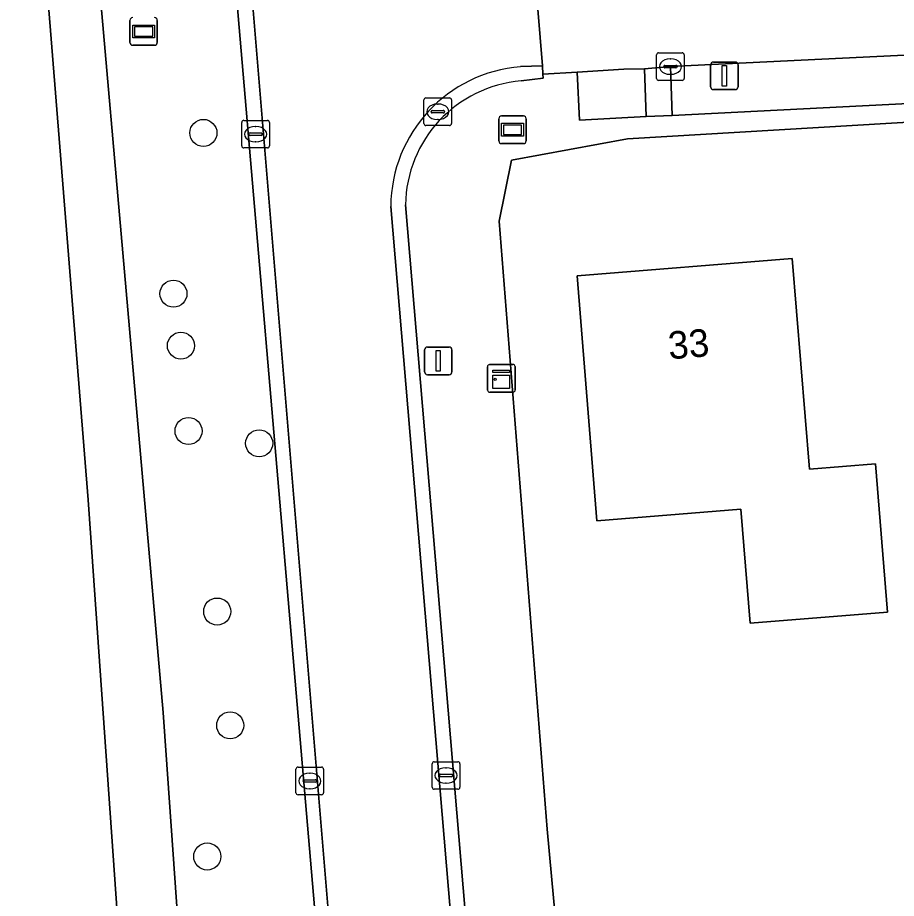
# Model space of a CAD drawing. Extents: x 162661 to 163484, y 380247 to 381230.
# Drawn here: x 163096.7 to 163128.5, y 380681.45 to 380713.34 of the extents above; entities that cross this region are included whole.
import ezdxf

# ---------------------------------------------------------------- set-up
doc = ezdxf.new("R2010")
doc.units = 0
for name, color, linetype in [('IMGEO_Boom', 7, 'Continuous'), ('IMGEO_Erf', 7, 'Continuous'), ('IMGEO_Groenvoorziening', 7, 'Continuous'), ('IMGEO_Kast', 7, 'Continuous'), ('IMGEO_Kolk', 7, 'Continuous'), ('IMGEO_Lichtmast', 7, 'Continuous'), ('IMGEO_Pand', 7, 'Continuous'), ('IMGEO_Pand_nummerreeks', 7, 'Continuous'), ('IMGEO_Parkeervlak_halfverhard', 7, 'Continuous'), ('IMGEO_Rijbaan_lokaal_gesloten', 7, 'Continuous'), ('IMGEO_Rijbaan_lokaal_open', 7, 'Continuous'), ('IMGEO_Straatnaambord', 7, 'Continuous'), ('IMGEO_Verklikker', 7, 'Continuous'), ('IMGEO_Voetpad_open', 7, 'Continuous')]:
    doc.layers.add(name, color=color, linetype=linetype)

msp = doc.modelspace()

# ---------------------------------------------------------------- linework, layer by layer
at = {"layer": 'IMGEO_Boom'}
for centre in [(163103.422, 380709.163), (163102.337, 380703.343), (163102.606, 380701.459), (163102.882, 380698.371), (163105.439, 380697.926), (163103.92, 380691.838), (163104.39, 380687.716), (163103.559, 380682.97)]:
    msp.add_circle(centre, 0.489, dxfattribs=at)
at = {"layer": 'IMGEO_Erf'}
for points in [[(163099.255, 380695.881), (163097.801, 380713.922), (163097.793, 380714.023), (163096.429, 380713.908), (163093.637, 380713.673), (163059.39, 380710.863), (163058.898, 380719.038), (163058.632, 380719.002), (163032.944, 380715.524), (163037.315, 380653.943), (163063.757, 380657.004), (163064.055, 380657.039), (163063.669, 380662.881), (163100.129, 380668.22), (163101.186, 380668.378), (163101.16, 380668.743)], [(163123.212, 380691.412), (163122.877, 380695.542), (163117.662, 380695.119), (163116.944, 380703.984), (163124.734, 380704.615), (163125.352, 380696.988), (163127.743, 380697.181), (163128.178, 380691.814)]]:
    msp.add_lwpolyline(points, close=True, dxfattribs=at)
msp.add_lwpolyline([(163169.175, 380712.083), (163165.538, 380711.722), (163118.769, 380708.949), (163114.577, 380708.178), (163114.12, 380705.969), (163115.857, 380683.956), (163117.643, 380664.6), (163117.707, 380663.313), (163117.885, 380659.75), (163116.14, 380660.353), (163114.938, 380658.973), (163115.539, 380658.257), (163116.937, 380656.59), (163121.165, 380651.709), (163126.069, 380600.194)], dxfattribs=at)
at = {"layer": 'IMGEO_Groenvoorziening'}
msp.add_lwpolyline([(163104.682, 380713.401), (163104.584, 380714.593), (163103.718, 380714.52), (163103.473, 380714.5), (163099.679, 380714.181), (163101.96, 380688.185), (163103.318, 380669.012), (163103.34, 380668.7), (163107.281, 380669.289), (163107.167, 380670.648), (163108.355, 380670.753), (163107.991, 380674.665)], close=True, dxfattribs=at)
for points in [[(163115.857, 380683.956), (163114.12, 380705.969), (163114.577, 380708.178), (163118.769, 380708.949), (163165.538, 380711.722), (163165.457, 380712.44), (163162.021, 380712.179), (163153.17, 380711.561), (163152.219, 380711.484), (163142.245, 380710.899), (163120.382, 380709.791), (163119.45, 380709.752), (163117.031, 380709.623), (163116.953, 380711.361), (163115.709, 380711.284), (163115.715, 380711.141), (163114.917, 380711.042)], [(163110.734, 380706.554), (163112.985, 380679.977), (163114.376, 380665.012), (163117.707, 380663.313), (163117.643, 380664.6), (163115.857, 380683.956)]]:
    msp.add_lwpolyline(points, dxfattribs=at)
msp.add_arc((163115.301, 380706.491), 4.568, 94.8247, 179.2044, dxfattribs=at)
at = {"layer": 'IMGEO_Kast'}
for p, q in [((163113.778, 380700.779), (163114.619, 380700.779)), ((163114.619, 380700.779), (163113.778, 380700.779)), ((163113.703, 380699.854), (163113.703, 380700.695)), ((163113.703, 380700.695), (163113.703, 380699.854)), ((163114.703, 380700.704), (163114.703, 380699.863)), ((163114.703, 380699.863), (163114.703, 380700.704)), ((163114.628, 380699.779), (163113.787, 380699.779)), ((163113.787, 380699.779), (163114.628, 380699.779))]:
    msp.add_line(p, q, dxfattribs=at)
for points in [[(163113.898, 380700.569), (163114.498, 380700.569), (163114.498, 380700.484), (163113.898, 380700.484), (163113.898, 380700.569)], [(163113.898, 380700.394), (163114.498, 380700.394), (163114.498, 380699.905), (163113.898, 380699.905), (163113.898, 380700.394)]]:
    msp.add_lwpolyline(points, dxfattribs=at)
msp.add_circle((163113.982, 380700.243), 0.0377, dxfattribs=at)
for centre, start, end in [((163113.781, 380700.701), 92.4484, 184.2845), ((163113.781, 380700.701), 92.4484, 184.2845), ((163114.625, 380700.701), 2.4484, 94.2845), ((163114.625, 380700.701), 2.4484, 94.2845), ((163113.781, 380699.857), 182.4484, 274.2845), ((163113.781, 380699.857), 182.4484, 274.2845), ((163114.625, 380699.857), 272.4484, 4.2845), ((163114.625, 380699.857), 272.4484, 4.2845)]:
    msp.add_arc(centre, 0.0779, start, end, dxfattribs=at)
at = {"layer": 'IMGEO_Kolk'}
for p, q in [((163119.823, 380711.137), (163119.823, 380711.989)), ((163119.898, 380712.063), (163120.75, 380712.063)), ((163120.824, 380711.989), (163120.824, 380711.137)), ((163120.311, 380711.843), (163120.336, 380711.843)), ((163120.082, 380711.557), (163120.082, 380711.569)), ((163120.52, 380711.52), (163120.122, 380711.52)), ((163120.125, 380711.606), (163120.523, 380711.606)), ((163120.566, 380711.569), (163120.566, 380711.557)), ((163120.75, 380711.063), (163119.898, 380711.063)), ((163120.334, 380711.283), (163120.309, 380711.283)), ((163111.402, 380709.502), (163111.402, 380710.354)), ((163111.477, 380710.428), (163112.329, 380710.428)), ((163112.403, 380710.354), (163112.403, 380709.502)), ((163111.89, 380710.208), (163111.915, 380710.208)), ((163111.661, 380709.922), (163111.661, 380709.934)), ((163112.099, 380709.885), (163111.701, 380709.885)), ((163111.704, 380709.971), (163112.102, 380709.971)), ((163112.145, 380709.934), (163112.145, 380709.922)), ((163104.81, 380708.691), (163104.81, 380709.543)), ((163104.885, 380709.617), (163105.737, 380709.617)), ((163105.298, 380709.397), (163105.323, 380709.397)), ((163105.811, 380709.543), (163105.811, 380708.691)), ((163112.329, 380709.428), (163111.477, 380709.428)), ((163111.913, 380709.648), (163111.888, 380709.648)), ((163105.069, 380709.111), (163105.069, 380709.123)), ((163105.507, 380709.074), (163105.109, 380709.074)), ((163105.112, 380709.16), (163105.51, 380709.16)), ((163105.553, 380709.123), (163105.553, 380709.111)), ((163105.321, 380708.837), (163105.296, 380708.837)), ((163105.737, 380708.617), (163104.885, 380708.617)), ((163106.77, 380685.278), (163106.77, 380686.13)), ((163106.845, 380686.204), (163107.697, 380686.204)), ((163107.771, 380686.13), (163107.771, 380685.278)), ((163111.701, 380685.476), (163111.701, 380686.328)), ((163111.776, 380686.402), (163112.628, 380686.402)), ((163112.189, 380686.182), (163112.214, 380686.182)), ((163112.702, 380686.328), (163112.702, 380685.476)), ((163107.258, 380685.984), (163107.283, 380685.984)), ((163111.96, 380685.896), (163111.96, 380685.908)), ((163112.398, 380685.859), (163112, 380685.859)), ((163112.003, 380685.945), (163112.401, 380685.945)), ((163112.444, 380685.908), (163112.444, 380685.896)), ((163107.029, 380685.698), (163107.029, 380685.71)), ((163107.467, 380685.661), (163107.069, 380685.661)), ((163107.072, 380685.747), (163107.47, 380685.747)), ((163107.513, 380685.71), (163107.513, 380685.698)), ((163112.212, 380685.622), (163112.187, 380685.622)), ((163107.697, 380685.204), (163106.845, 380685.204)), ((163107.281, 380685.424), (163107.256, 380685.424)), ((163112.628, 380685.402), (163111.776, 380685.402))]:
    msp.add_line(p, q, dxfattribs=at)
for points in [[(163119.823, 380711.137), (163119.823, 380711.989)], [(163119.898, 380712.063), (163120.75, 380712.063)], [(163120.824, 380711.989), (163120.824, 380711.137)], [(163120.75, 380711.063), (163119.898, 380711.063)], [(163111.402, 380709.502), (163111.402, 380710.354)], [(163111.477, 380710.428), (163112.329, 380710.428)], [(163112.403, 380710.354), (163112.403, 380709.502)], [(163104.81, 380708.691), (163104.81, 380709.543)], [(163104.885, 380709.617), (163105.737, 380709.617)], [(163105.811, 380709.543), (163105.811, 380708.691)], [(163112.329, 380709.428), (163111.477, 380709.428)], [(163105.737, 380708.617), (163104.885, 380708.617)], [(163106.77, 380685.278), (163106.77, 380686.13)], [(163106.845, 380686.204), (163107.697, 380686.204)], [(163107.771, 380686.13), (163107.771, 380685.278)], [(163111.701, 380685.476), (163111.701, 380686.328)], [(163111.776, 380686.402), (163112.628, 380686.402)], [(163112.702, 380686.328), (163112.702, 380685.476)], [(163107.697, 380685.204), (163106.845, 380685.204)], [(163112.628, 380685.402), (163111.776, 380685.402)]]:
    msp.add_lwpolyline(points, dxfattribs=at)
for centre, radius, start, end in [((163119.9, 380711.987), 0.0765, 91.552, 178.448), ((163119.9, 380711.987), 0.0765, 91.552, 178.448), ((163120.748, 380711.987), 0.0765, 1.552, 88.448), ((163120.748, 380711.987), 0.0765, 1.552, 88.448), ((163120.122, 380711.566), 0.0403, 85.8775, 175.7526), ((163120.119, 380711.556), 0.0366, 178.938, 274.7102), ((163120.523, 380711.563), 0.043, 264.8664, 352.4533), ((163120.527, 380711.568), 0.0386, 1.7309, 96.639), ((163119.9, 380711.139), 0.0765, 181.552, 268.448), ((163119.9, 380711.139), 0.0765, 181.552, 268.448), ((163120.748, 380711.139), 0.0765, 271.552, 358.448), ((163120.748, 380711.139), 0.0765, 271.552, 358.448), ((163111.479, 380710.352), 0.0765, 91.552, 178.448), ((163111.479, 380710.352), 0.0765, 91.552, 178.448), ((163112.327, 380710.352), 0.0765, 1.552, 88.448), ((163112.327, 380710.352), 0.0765, 1.552, 88.448), ((163111.701, 380709.931), 0.0403, 85.8775, 175.7526), ((163111.698, 380709.921), 0.0366, 178.938, 274.7102), ((163112.102, 380709.928), 0.043, 264.8664, 352.4533), ((163112.106, 380709.933), 0.0386, 1.7309, 96.639), ((163104.887, 380709.541), 0.0765, 91.552, 178.448), ((163104.887, 380709.541), 0.0765, 91.552, 178.448), ((163105.735, 380709.541), 0.0765, 1.552, 88.448), ((163105.735, 380709.541), 0.0765, 1.552, 88.448), ((163111.479, 380709.504), 0.0765, 181.552, 268.448), ((163111.479, 380709.504), 0.0765, 181.552, 268.448), ((163112.327, 380709.504), 0.0765, 271.552, 358.448), ((163112.327, 380709.504), 0.0765, 271.552, 358.448), ((163105.109, 380709.12), 0.0403, 85.8775, 175.7526), ((163105.106, 380709.11), 0.0366, 178.938, 274.7102), ((163105.51, 380709.117), 0.043, 264.8664, 352.4533), ((163105.514, 380709.122), 0.0386, 1.7309, 96.639), ((163104.887, 380708.693), 0.0765, 181.552, 268.448), ((163104.887, 380708.693), 0.0765, 181.552, 268.448), ((163105.735, 380708.693), 0.0765, 271.552, 358.448), ((163105.735, 380708.693), 0.0765, 271.552, 358.448), ((163106.847, 380686.128), 0.0765, 91.552, 178.448), ((163106.847, 380686.128), 0.0765, 91.552, 178.448), ((163107.695, 380686.128), 0.0765, 1.552, 88.448), ((163107.695, 380686.128), 0.0765, 1.552, 88.448), ((163111.778, 380686.326), 0.0765, 91.552, 178.448), ((163111.778, 380686.326), 0.0765, 91.552, 178.448), ((163112.626, 380686.326), 0.0765, 1.552, 88.448), ((163112.626, 380686.326), 0.0765, 1.552, 88.448), ((163112, 380685.905), 0.0403, 85.8775, 175.7526), ((163111.997, 380685.895), 0.0366, 178.938, 274.7102), ((163112.401, 380685.902), 0.043, 264.8664, 352.4533), ((163112.405, 380685.907), 0.0386, 1.7309, 96.639), ((163107.069, 380685.707), 0.0403, 85.8775, 175.7526), ((163107.066, 380685.697), 0.0366, 178.938, 274.7102), ((163107.47, 380685.704), 0.043, 264.8664, 352.4533), ((163107.474, 380685.709), 0.0386, 1.7309, 96.639), ((163111.778, 380685.478), 0.0765, 181.552, 268.448), ((163111.778, 380685.478), 0.0765, 181.552, 268.448), ((163112.626, 380685.478), 0.0765, 271.552, 358.448), ((163112.626, 380685.478), 0.0765, 271.552, 358.448), ((163106.847, 380685.28), 0.0765, 181.552, 268.448), ((163106.847, 380685.28), 0.0765, 181.552, 268.448), ((163107.695, 380685.28), 0.0765, 271.552, 358.448), ((163107.695, 380685.28), 0.0765, 271.552, 358.448)]:
    msp.add_arc(centre, radius, start, end, dxfattribs=at)
for centre, major_axis, ratio, start_param, end_param in [((163120.31, 380711.563), (-0.387, 0.002), 0.722429, 4.712389, 7.853982), ((163120.335, 380711.563), (-0.39, 0.002), 0.717154, 1.570796, 4.712389), ((163111.889, 380709.928), (-0.387, 0.002), 0.722429, 4.712389, 7.853982), ((163111.914, 380709.928), (-0.39, 0.002), 0.717154, 1.570796, 4.712389), ((163105.297, 380709.117), (-0.387, 0.002), 0.722429, 4.712389, 7.853982), ((163105.322, 380709.117), (-0.39, 0.002), 0.717154, 1.570796, 4.712389), ((163112.188, 380685.902), (-0.387, 0.002), 0.722429, 4.712389, 7.853982), ((163112.213, 380685.902), (-0.39, 0.002), 0.717154, 1.570796, 4.712389), ((163107.257, 380685.704), (-0.387, 0.002), 0.722429, 4.712389, 7.853982), ((163107.282, 380685.704), (-0.39, 0.002), 0.717154, 1.570796, 4.712389)]:
    msp.add_ellipse(centre, major_axis=major_axis, ratio=ratio, start_param=start_param, end_param=end_param, dxfattribs=at)
at = {"layer": 'IMGEO_Lichtmast'}
for p, q in [((163121.78, 380710.828), (163121.78, 380711.628)), ((163121.78, 380711.628), (163121.78, 380710.828)), ((163121.88, 380711.728), (163122.67, 380711.728)), ((163122.67, 380711.728), (163121.88, 380711.728)), ((163122.77, 380711.628), (163122.77, 380710.828)), ((163122.77, 380710.828), (163122.77, 380711.628)), ((163122.67, 380710.728), (163121.88, 380710.728)), ((163121.88, 380710.728), (163122.67, 380710.728)), ((163111.526, 380701.411), (163112.316, 380701.411)), ((163112.316, 380701.411), (163111.526, 380701.411)), ((163111.426, 380700.511), (163111.426, 380701.311)), ((163111.426, 380701.311), (163111.426, 380700.511)), ((163112.416, 380701.311), (163112.416, 380700.511)), ((163112.416, 380700.511), (163112.416, 380701.311)), ((163112.316, 380700.411), (163111.526, 380700.411)), ((163111.526, 380700.411), (163112.316, 380700.411))]:
    msp.add_line(p, q, dxfattribs=at)
for points in [[(163122.2, 380711.603), (163122.35, 380711.603), (163122.35, 380710.853), (163122.2, 380710.853), (163122.2, 380711.603)], [(163111.846, 380701.286), (163111.996, 380701.286), (163111.996, 380700.536), (163111.846, 380700.536), (163111.846, 380701.286)]]:
    msp.add_lwpolyline(points, dxfattribs=at)
for centre, start, end in [((163121.88, 380711.628), 90, 180), ((163121.88, 380711.628), 90, 180), ((163122.67, 380711.628), 0, 90), ((163122.67, 380711.628), 360, 90), ((163121.88, 380710.828), 180, 270), ((163121.88, 380710.828), 180, 270), ((163122.67, 380710.828), 270, 0), ((163122.67, 380710.828), 270, 0), ((163111.526, 380701.311), 90, 180), ((163111.526, 380701.311), 90, 180), ((163112.316, 380701.311), 0, 90), ((163112.316, 380701.311), 360, 90), ((163111.526, 380700.511), 180, 270), ((163111.526, 380700.511), 180, 270), ((163112.316, 380700.511), 270, 0), ((163112.316, 380700.511), 270, 0)]:
    msp.add_arc(centre, 0.1, start, end, dxfattribs=at)
at = {"layer": 'IMGEO_Pand'}
msp.add_lwpolyline([(163123.212, 380691.412), (163128.178, 380691.814), (163127.743, 380697.181), (163125.352, 380696.988), (163124.734, 380704.615), (163116.944, 380703.984), (163117.662, 380695.119), (163122.877, 380695.542)], close=True, dxfattribs=at)
at = {"layer": 'IMGEO_Parkeervlak_halfverhard'}
for points in [[(163152.095, 380713.243), (163142.232, 380712.632), (163120.324, 380711.563), (163120.382, 380709.791), (163142.245, 380710.899), (163152.219, 380711.484)], [(163119.381, 380711.482), (163118.64, 380711.465), (163116.953, 380711.361), (163117.031, 380709.623), (163119.45, 380709.752)]]:
    msp.add_lwpolyline(points, close=True, dxfattribs=at)
at = {"layer": 'IMGEO_Rijbaan_lokaal_gesloten'}
for points in [[(163109.01, 380721.262), (163105.557, 380762.775), (163101.152, 380762.413), (163108.051, 380679.583), (163111.151, 380646.231), (163112.81, 380644.864)], [(163131.643, 380717.729), (163128.093, 380717.58), (163119.903, 380717.14), (163118.28, 380717.058), (163115.275, 380716.881), (163115.281, 380716.591), (163115.697, 380711.596), (163115.709, 380711.284), (163116.953, 380711.361), (163118.64, 380711.465), (163119.381, 380711.482), (163120.324, 380711.563), (163142.232, 380712.632), (163152.095, 380713.243), (163153.006, 380713.282), (163162.041, 380713.929), (163165.261, 380714.182), (163168.921, 380714.47), (163174.22, 380714.886)], [(163114.9, 380711.56), (163115.697, 380711.596), (163115.281, 380716.591), (163114.725, 380716.563)], [(163112.449, 380679.916), (163110.203, 380706.499)]]:
    msp.add_lwpolyline(points, dxfattribs=at)
msp.add_arc((163115.306, 380706.473), 5.103, 94.5623, 179.7103, dxfattribs=at)
at = {"layer": 'IMGEO_Rijbaan_lokaal_open'}
for points in [[(163101.152, 380762.413), (163100.826, 380762.387), (163100.872, 380761.825), (163100.666, 380761.794), (163102.908, 380735.018), (163103.02, 380733.686), (163103.303, 380730.246), (163104.301, 380718.051), (163104.584, 380714.593), (163104.682, 380713.401), (163107.991, 380674.665), (163108.355, 380670.753), (163108.475, 380669.468), (163108.8, 380665.991), (163109.973, 380653.239), (163110.29, 380649.787), (163110.409, 380648.484), (163110.502, 380647.474)], [(163111.151, 380646.231), (163108.051, 380679.583), (163101.152, 380762.413)], [(163114.917, 380711.042), (163115.715, 380711.141), (163115.709, 380711.284), (163115.697, 380711.596), (163114.9, 380711.56)], [(163115.767, 380650.09), (163114.938, 380658.973), (163114.376, 380665.012), (163112.985, 380679.977), (163110.734, 380706.554)], [(163110.203, 380706.499), (163112.449, 380679.916), (163116.651, 380635.796)]]:
    msp.add_lwpolyline(points, dxfattribs=at)
for centre, radius, start, end in [((163115.306, 380706.473), 5.103, 94.5623, 179.7103), ((163115.301, 380706.491), 4.568, 94.8247, 179.2044)]:
    msp.add_arc(centre, radius, start, end, dxfattribs=at)
at = {"layer": 'IMGEO_Straatnaambord'}
for p, q in [((163100.763, 380712.436), (163100.763, 380713.236)), ((163100.763, 380713.236), (163100.763, 380712.436)), ((163101.753, 380713.236), (163101.753, 380712.436)), ((163101.753, 380712.436), (163101.753, 380713.236)), ((163101.653, 380712.336), (163100.863, 380712.336)), ((163100.863, 380712.336), (163101.653, 380712.336))]:
    msp.add_line(p, q, dxfattribs=at)
for points in [[(163100.864, 380713.068), (163101.652, 380713.068), (163101.652, 380712.604), (163100.864, 380712.604), (163100.864, 380713.068)], [(163100.929, 380713.003), (163100.929, 380712.669), (163101.587, 380712.669), (163101.587, 380713.003), (163100.929, 380713.003)]]:
    msp.add_lwpolyline(points, dxfattribs=at)
for centre, start, end in [((163100.863, 380713.236), 90, 180), ((163100.863, 380713.236), 90, 180), ((163101.653, 380713.236), 0, 90), ((163101.653, 380713.236), 360, 90), ((163100.863, 380712.436), 180, 270), ((163100.863, 380712.436), 180, 270), ((163101.653, 380712.436), 270, 0), ((163101.653, 380712.436), 270, 0)]:
    msp.add_arc(centre, 0.1, start, end, dxfattribs=at)
at = {"layer": 'IMGEO_Verklikker'}
for p, q in [((163114.214, 380709.777), (163115.004, 380709.777)), ((163115.004, 380709.777), (163114.214, 380709.777)), ((163114.114, 380708.877), (163114.114, 380709.677)), ((163114.114, 380709.677), (163114.114, 380708.877)), ((163115.104, 380709.677), (163115.104, 380708.877)), ((163115.104, 380708.877), (163115.104, 380709.677)), ((163115.004, 380708.777), (163114.214, 380708.777)), ((163114.214, 380708.777), (163115.004, 380708.777))]:
    msp.add_line(p, q, dxfattribs=at)
for points in [[(163114.215, 380709.509), (163115.003, 380709.509), (163115.003, 380709.045), (163114.215, 380709.045), (163114.215, 380709.509)], [(163114.28, 380709.444), (163114.28, 380709.11), (163114.938, 380709.11), (163114.938, 380709.444), (163114.28, 380709.444)]]:
    msp.add_lwpolyline(points, dxfattribs=at)
for centre, start, end in [((163114.214, 380709.677), 90, 180), ((163114.214, 380709.677), 90, 180), ((163115.004, 380709.677), 0, 90), ((163115.004, 380709.677), 360, 90), ((163114.214, 380708.877), 180, 270), ((163114.214, 380708.877), 180, 270), ((163115.004, 380708.877), 270, 0), ((163115.004, 380708.877), 270, 0)]:
    msp.add_arc(centre, 0.1, start, end, dxfattribs=at)
at = {"layer": 'IMGEO_Voetpad_open'}
for points in [[(163101.186, 380668.378), (163103.34, 380668.7), (163103.318, 380669.012), (163101.96, 380688.185), (163099.679, 380714.181), (163097.793, 380714.023), (163097.801, 380713.922), (163099.255, 380695.881), (163101.16, 380668.743)], [(163120.382, 380709.791), (163120.324, 380711.563), (163119.381, 380711.482), (163119.45, 380709.752)]]:
    msp.add_lwpolyline(points, close=True, dxfattribs=at)

# ---------------------------------------------------------------- texts
at = {"layer": 'IMGEO_Pand_nummerreeks'}
msp.add_text('33', height=1, rotation=4.6309, dxfattribs=at).set_placement((163120.28, 380700.964))

doc.saveas('drawing.dxf')
